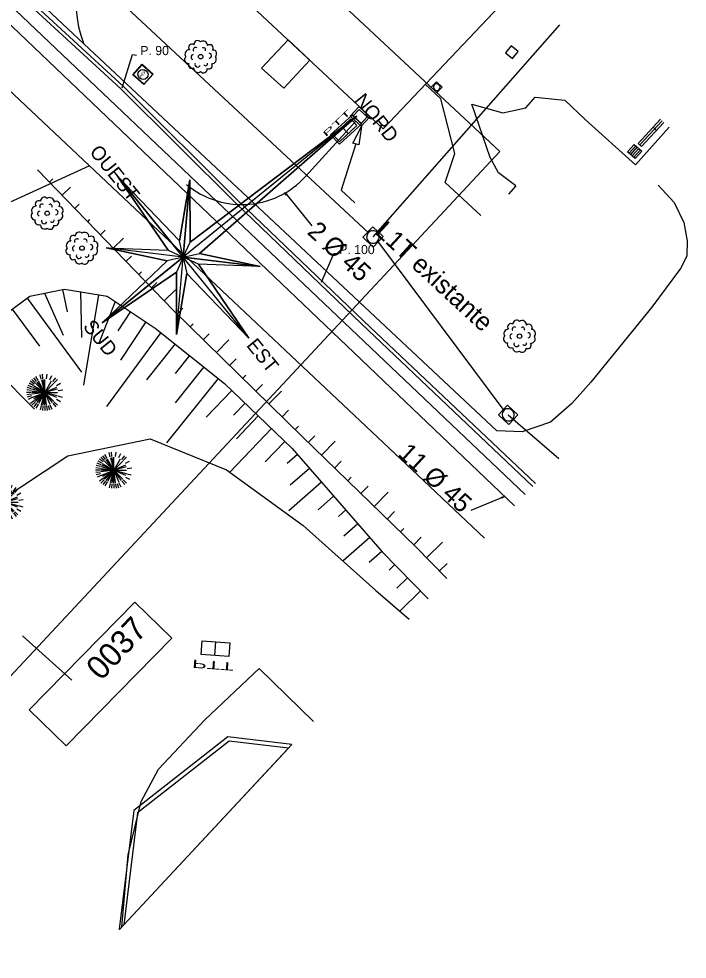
# Model space of a CAD drawing. Extents: x 343997 to 344255, y 298512 to 298767.
# Drawn here: x 344218.9 to 344255.3, y 298581.7 to 298632.9 of the extents above; entities that cross this region are included whole.
import ezdxf

# ---------------------------------------------------------------- set-up
doc = ezdxf.new("R2010")
doc.units = 0
for name, color, linetype in [('Default', 7, 'Continuous'), ('DH_CADRE -CARTOUCHE', 7, 'Continuous'), ('DH_CADRE-CARTOUCHE', 7, 'Continuous'), ('DH_CADRE-CARTOUCHE-NORD', 7, 'Continuous'), ('DH_NORD', 7, 'Continuous'), ('DH_TEXTE', 7, 'Continuous'), ('DIR-Projet VRD1', 7, 'Continuous'), ('EL-FOURR', 7, 'Continuous'), ('GO_DALLE', 7, 'Continuous'), ('IMM_VOIRIE VOIE FERREE', 7, 'Continuous'), ('MT-DONNEE', 7, 'Continuous'), ('O-Projet New VRD', 7, 'Continuous'), ('PC_REBAR', 7, 'Continuous'), ('PS_HIDDEN', 7, 'Continuous'), ('PS_OBJECT', 7, 'Continuous'), ('PS_PLATE', 7, 'Continuous'), ('RES_EAU', 7, 'Continuous'), ('RES_EAU PLUVIALE', 7, 'Continuous'), ('RES_MOYENNE TENSION', 7, 'Continuous')]:
    doc.layers.add(name, color=color, linetype=linetype)

# ---------------------------------------------------------------- blocks, each defined once
blk = doc.blocks.new('REG_INC')
at = {"layer": 'Default'}
for p, q in [((0, 0.1), (0.1, 0.1)), ((0, 0), (0, 0.1)), ((0.1, 0.1), (0.1, 0)), ((0.1, 0), (0, 0))]:
    blk.add_line(p, q, dxfattribs=at)
for centre, start, end in [((0.0498, 0.05), 135.00554, 180.00554), ((0.05, 0.0498), 90.00577, 135.00577), ((0.05, 0.05), 45.00687, 90.00687), ((0.0499, 0.0499), 0.00663, 45.00663), ((0.0501, 0.05), 180.00663, 225.00663), ((0.0499, 0.0498), 225.00686, 270.00686), ((0.0499, 0.05), 270.00577, 315.00577), ((0.0501, 0.0499), 315.00554, 0.00554)]:
    blk.add_arc(centre, 0.044, start, end, dxfattribs=at)
blk = doc.blocks.new('R3')
at = {"layer": 'Default'}
for p, q in [((0, 0.1), (0.1, 0.1)), ((0, 0), (0, 0.1)), ((0.1, 0), (0, 0)), ((0.1, 0.1), (0.1, 0))]:
    blk.add_line(p, q, dxfattribs=at)
blk = doc.blocks.new('RES_EAU')
at = {"layer": 'RES_EAU'}
for points in [[(0, 0), (0, 0.1), (0.1, 0.1), (0.1, 0)], [(0.0025, 0.0025), (0.0025, 0.0975), (0.0975, 0.0975), (0.0975, 0.0025)]]:
    blk.add_lwpolyline(points, close=True, dxfattribs=at)
blk.add_circle((0.05, 0.05), 0.035, dxfattribs=at)
blk.add_text('AEP', height=0.02, dxfattribs=at).set_placement((0.0224, 0.0448))
blk = doc.blocks.new('CT2')
at = {"layer": 'Default'}
blk.add_lwpolyline([(0, 0), (0.1, 0), (0.1, 0.1), (0, 0.1)], close=True, dxfattribs=at)
blk.add_lwpolyline([(0.05, 0.1), (0.05, 0)], dxfattribs=at)
blk.add_text('PTT', height=0.06, dxfattribs=at).set_placement((-0.03, 0.1425))
blk = doc.blocks.new('R5')
at = {"layer": 'Default'}
for p, q in [((0, 0.1), (0, 0)), ((0.1, 0.1), (0, 0.1)), ((0.02, 0.1), (0.02, 0)), ((0.04, 0.1), (0.04, 0)), ((0.06, 0.1), (0.06, 0)), ((0.08, 0.1), (0.08, 0)), ((0.1, 0), (0.1, 0.1)), ((0, 0), (0.1, 0)), ((0.06, 0), (0.06, 0))]:
    blk.add_line(p, q, dxfattribs=at)
blk = doc.blocks.new('ARB1')
at = {"layer": 'Default'}
blk.add_circle((0, 0), 0.0122, dxfattribs=at)
for centre, radius, start, end in [((-0.0471, 0.0503), 0.0183, 53.9554, 222.2066), ((-0.0153, 0.0664), 0.0211, 43.6925, 183.5969), ((0.0139, 0.0613), 0.0241, 358.4583, 125.1928), ((0.0501, 0.0468), 0.0183, 325.1444, 131.0175), ((-0.0613, 0.0139), 0.0241, 88.4583, 215.1928), ((-0.0373, -0.0024), 0.0149, 103.7092, 242.3465), ((-0.0276, 0.037), 0.0134, 52.4396, 209.5496), ((0.0164, 0.038), 0.0112, 330.5895, 133.7127), ((0.0458, 0.0052), 0.0137, 276.6214, 88.967), ((0.0613, -0.0139), 0.0241, 268.4583, 35.1928), ((0.0664, 0.0153), 0.0211, 313.6925, 93.5969), ((-0.0664, -0.0153), 0.0211, 133.6925, 273.5969), ((-0.0478, -0.0443), 0.019, 155.2243, 300.9377), ((-0.0163, -0.042), 0.0148, 159.5371, 338.1663), ((0.0271, -0.038), 0.0112, 210.5895, 13.7127), ((0.0448, -0.0483), 0.0188, 243.1323, 33.0297), ((-0.0139, -0.0613), 0.0241, 178.4583, 305.1928), ((0.0153, -0.0664), 0.0211, 223.6925, 3.5969)]:
    blk.add_arc(centre, radius, start, end, dxfattribs=at)
blk = doc.blocks.new('ARB2')
at = {"layer": 'Default'}
for p, q in [((-0.0575, 0.0453), (-0.0775, 0.0605)), ((-0.0513, 0.0525), (-0.0688, 0.0702)), ((-0.0438, 0.0589), (-0.0588, 0.0786)), ((-0.0356, 0.0642), (-0.0481, 0.0858)), ((-0.0181, 0.0716), (-0.0244, 0.0956)), ((-0.0088, 0.0736), (-0.0119, 0.0983)), ((0.0106, 0.0736), (0.0144, 0.0983)), ((0.0287, 0.0684), (0.0388, 0.0914)), ((0.0456, 0.0589), (0.0612, 0.0786)), ((0.0531, 0.0525), (0.0706, 0.0702)), ((-0.0731, 0), (-0.0981, 0)), ((-0.0725, 0.01), (-0.0969, 0.0133)), ((-0.0706, 0.0195), (-0.0944, 0.0259)), ((-0.0675, 0.0286), (-0.09, 0.0381)), ((-0.0631, 0.0373), (-0.0844, 0.0497)), ((0.065, 0.0373), (0.0862, 0.0497)), ((0.0744, 0.01), (0.0987, 0.0133)), ((-0.0725, -0.01), (-0.0969, -0.0133)), ((-0.0706, -0.0195), (-0.0944, -0.0259)), ((-0.0675, -0.0287), (-0.09, -0.0383)), ((-0.0575, -0.0455), (-0.0775, -0.0605)), ((0.065, -0.0373), (0.0862, -0.0498)), ((0.0725, -0.0195), (0.0963, -0.0259)), ((-0.0513, -0.0527), (-0.0688, -0.0702)), ((-0.0438, -0.0591), (-0.0588, -0.0787)), ((-0.0356, -0.0644), (-0.0481, -0.0859)), ((-0.0181, -0.0717), (-0.0244, -0.0956)), ((-0.0088, -0.0737), (-0.0119, -0.0983)), ((0.0013, -0.0741), (0.0013, -0.0989)), ((0.0106, -0.0737), (0.0144, -0.0983)), ((0.02, -0.0717), (0.0263, -0.0956)), ((0.0287, -0.0686), (0.0388, -0.0916)), ((0.0456, -0.0591), (0.0612, -0.0787)), ((0.0531, -0.0527), (0.0706, -0.0702))]:
    blk.add_line(p, q, dxfattribs=at)
for points in [[(-0.0688, 0.0091), (0.0013, 0), (-0.0338, 0.0608)], [(-0.0419, 0.0556), (0.0013, 0), (-0.0638, 0.0269)], [(-0.0169, 0.0677), (0.0013, 0), (-0.06, 0.035)], [(0.0013, 0.0008), (0.0013, 0), (-0.0081, 0.0695)], [(0.0362, 0.0608), (0.0013, 0), (0.0013, 0.0702)], [(-0.0487, -0.0497), (0.0013, 0), (-0.0694, 0)], [(-0.0638, -0.0269), (0.0013, 0), (-0.0688, -0.0092)], [(-0.0487, 0.0495), (0.0013, 0), (-0.0669, 0.0181)], [(-0.0169, -0.0678), (0.0013, 0), (-0.06, -0.0352)], [(-0.0544, -0.0428), (0.0013, 0), (-0.0338, -0.0608)], [(-0.0081, -0.0695), (0.0013, 0), (-0.0419, -0.0558)], [(0.0013, -0.0702), (0.0013, 0), (0, 0)], [(0.0656, 0.0269), (0.0013, 0), (0.0506, 0.0495)], [(0.0688, 0.0181), (0.0013, 0), (0.0713, 0)], [(0.0438, -0.0558), (0.0013, 0), (0.0656, -0.0269)], [(0.0506, -0.0497), (0.0013, 0), (0.0688, -0.0181)], [(0.01, -0.0695), (0.0013, 0), (0.0281, -0.0648)], [(0.0019, 0), (0.0013, 0), (0.0013, -0.0009)]]:
    blk.add_lwpolyline(points, dxfattribs=at)

msp = doc.modelspace()

# ---------------------------------------------------------------- linework, layer by layer
at = {"layer": 'DH_CADRE -CARTOUCHE'}
for points in [[(343997.309, 298660.673), (344147.183, 298520.807), (344245.09, 298625.72), (344095.215, 298765.586)], [(344246.085, 298634.723), (344238.071, 298642.203), (344230.773, 298634.4), (344238.733, 298626.952)], [(344224.371, 298583.346), (344233.763, 298593.411), (344230.272, 298593.836), (344225.143, 298589.82), (344224.357, 298583.363)]]:
    msp.add_lwpolyline(points, close=True, dxfattribs=at)
at = {"layer": 'DH_CADRE-CARTOUCHE'}
for points in [[(344173.884, 298668.877), (344175.641, 298668.318), (344176.928, 298667.79), (344178.107, 298666.872), (344194.798, 298651.17), (344217.989, 298629.411), (344240.944, 298607.781), (344244.256, 298604.654)], [(344253.72, 298623.882), (344254.601, 298622.951), (344255.115, 298621.851), (344255.304, 298620.858), (344255.289, 298620.014), (344254.937, 298619.35), (344253.379, 298617.242), (344250.056, 298613.162), (344249.016, 298611.996), (344247.858, 298610.985), (344246.303, 298610.451), (344244.928, 298610.512), (344219.242, 298634.584), (344198.152, 298654.571), (344186.596, 298665.445)]]:
    msp.add_lwpolyline(points, dxfattribs=at)
msp.add_arc((344228.199, 298633.832), 6.201, 132.5787, 200.9263, dxfattribs=at)
at = {"layer": 'DH_CADRE-CARTOUCHE-NORD'}
for p, q in [((344248.345, 298632.614), (344238.179, 298621.064)), ((344215.714, 298621.751), (344222.758, 298624.96)), ((344238.423, 298620.831), (344245.304, 298611.605)), ((344245.555, 298611.367), (344248.309, 298608.997))]:
    msp.add_line(p, q, dxfattribs=at)
msp.add_lwpolyline([(344237.935, 298621.298), (344195.027, 298661.228), (344177.442, 298676.027), (344168.974, 298681.087)], dxfattribs=at)
at = {"layer": 'DH_NORD'}
for p, q in [((344237.303, 298627.646), (344223.425, 298616.384)), ((344237.303, 298627.646), (344228.217, 298620.788)), ((344224.257, 298624.374), (344227.011, 298620.345)), ((344231.415, 298615.553), (344224.257, 298624.374)), ((344227.465, 298615.748), (344228.206, 298624.179)), ((344228.206, 298624.179), (344227.644, 298620.859)), ((344223.634, 298620.469), (344226.962, 298619.77)), ((344232.037, 298619.458), (344223.634, 298620.469)), ((344232.037, 298619.458), (344228.721, 298620.167)), ((344231.415, 298615.553), (344228.673, 298619.592)), ((344223.425, 298616.384), (344227.466, 298619.149)), ((344227.465, 298615.748), (344228.039, 298619.078))]:
    msp.add_line(p, q, dxfattribs=at)
for points in [[(344237.303, 298627.646), (344228.721, 298620.167), (344232.037, 298619.458), (344228.673, 298619.592), (344231.415, 298615.553), (344228.039, 298619.078), (344227.465, 298615.748), (344227.466, 298619.149), (344223.425, 298616.384), (344226.962, 298619.77), (344223.634, 298620.469), (344227.011, 298620.345), (344224.257, 298624.374), (344227.644, 298620.859), (344228.206, 298624.179), (344228.217, 298620.788)], [(344237.303, 298627.646), (344227.836, 298619.963), (344228.721, 298620.167), (344228.721, 298620.167)], [(344224.257, 298624.374), (344227.836, 298619.963), (344227.644, 298620.859), (344227.644, 298620.859)], [(344228.206, 298624.179), (344227.836, 298619.963), (344228.217, 298620.788), (344228.217, 298620.788)], [(344223.634, 298620.469), (344227.011, 298620.345), (344227.836, 298619.963)], [(344223.425, 298616.384), (344227.836, 298619.963), (344226.962, 298619.77), (344226.962, 298619.77)], [(344227.465, 298615.748), (344227.836, 298619.963), (344227.466, 298619.149), (344227.466, 298619.149)], [(344232.037, 298619.458), (344228.673, 298619.592), (344227.836, 298619.963)], [(344231.415, 298615.553), (344227.836, 298619.963), (344228.039, 298619.078), (344228.039, 298619.078)]]:
    msp.add_lwpolyline(points, close=True, dxfattribs=at)
at = {"layer": 'DIR-Projet VRD1'}
msp.add_line((344180.02, 298669.219), (344245.896, 298606.412), dxfattribs=at)
msp.add_lwpolyline([(344237.239, 298627.37), (344234.681, 298624.557)], dxfattribs=at)
msp.add_arc((344231.037, 298627.539), 4.709, 230.0068, 320.7025, dxfattribs=at)
at = {"layer": 'EL-FOURR'}
for points in [[(344246.89, 298607.477), (344237.55, 298616.33), (344230.72, 298622.88), (344224.44, 298629.13), (344216.3, 298636.61), (344208.4, 298644.02), (344200.94, 298650.94), (344194.75, 298656.93), (344187.61, 298663.75), (344182.92, 298668.55), (344179.08, 298673.97)], [(344179.26, 298674.06), (344183.08, 298668.68), (344187.75, 298663.89), (344194.89, 298657.08), (344201.08, 298651.08), (344208.54, 298644.17), (344216.43, 298636.76), (344224.58, 298629.27), (344230.85, 298623.02), (344237.69, 298616.48), (344247.03, 298607.627)]]:
    msp.add_lwpolyline(points, dxfattribs=at)
at = {"layer": 'GO_DALLE'}
for points in [[(344234.735, 298630.693), (344233.554, 298631.798), (344232.114, 298630.26), (344233.317, 298629.178)], [(344237.059, 298627.718), (344237.552, 298627.211), (344236.363, 298626.128), (344235.87, 298626.636)]]:
    msp.add_lwpolyline(points, close=True, dxfattribs=at)
for points in [[(344244.061, 298622.24), (344242.123, 298624.038), (344242.65, 298625.603), (344241.87, 298628.59), (344241.032, 298629.382)], [(344245.974, 298623.847), (344245.03, 298624.565), (344244.572, 298625.398), (344243.566, 298628.301), (344245.252, 298627.821), (344246.504, 298628.1), (344247.021, 298628.689), (344248.634, 298628.526), (344249.747, 298627.457), (344252.49, 298624.988), (344254.319, 298627.04)], [(344245.974, 298623.847), (344245.561, 298623.405)]]:
    msp.add_lwpolyline(points, dxfattribs=at)
at = {"layer": 'IMM_VOIRIE VOIE FERREE'}
msp.add_line((344221.778, 298596.916), (344219.076, 298599.34), dxfattribs=at)
msp.add_lwpolyline([(344224.492, 298583.477), (344224.843, 298587.413), (344225.548, 298590.315), (344226.496, 298592.077), (344229.019, 298594.765), (344231.976, 298597.554), (344234.941, 298594.673)], dxfattribs=at)
at = {"layer": 'MT-DONNEE'}
for points in [[(344224.52, 298629.18), (344225.08, 298631), (344225.3, 298630.97)], [(344235.38, 298618.6), (344236.04, 298620.16), (344236.19, 298620.16)]]:
    msp.add_lwpolyline(points, dxfattribs=at)
at = {"layer": 'O-Projet New VRD'}
for points in [[(344237.42, 298628.155), (344238.007, 298627.614), (344237.533, 298627.099), (344236.944, 298627.641), (344237.419, 298628.156)], [(344237.428, 298628.017), (344237.869, 298627.611), (344237.531, 298627.242), (344237.089, 298627.649), (344237.428, 298628.017)], [(344237.248, 298626.13), (344236.449, 298623.607)], [(344236.449, 298623.607), (344237.185, 298622.93)], [(344233.481, 298623.354), (344234.842, 298621.676)], [(344245.186, 298606.861), (344243.521, 298606.159)]]:
    msp.add_lwpolyline(points, dxfattribs=at)
for points in [[(344237.089, 298626.18), (344237.55, 298627.084), (344237.407, 298626.08)], [(344233.458, 298623.335), (344233.368, 298623.494), (344233.505, 298623.373)], [(344245.174, 298606.888), (344245.352, 298606.931), (344245.197, 298606.833)]]:
    msp.add_lwpolyline(points, close=True, dxfattribs=at)
at = {"layer": 'PS_HIDDEN'}
msp.add_lwpolyline([(344224.608, 298583.6), (344233.577, 298593.212), (344230.336, 298593.606), (344225.35, 298589.703)], close=True, dxfattribs=at)
at = {"layer": 'PS_OBJECT'}
for p, q in [((344220.55, 298624.054), (344220.742, 298624.239)), ((344221.245, 298623.334), (344221.695, 298623.769)), ((344221.94, 298622.615), (344222.178, 298622.844)), ((344222.635, 298621.896), (344222.76, 298622.017)), ((344223.33, 298621.176), (344223.594, 298621.432)), ((344224.025, 298620.457), (344224.583, 298620.996)), ((344224.72, 298619.737), (344225.015, 298620.022)), ((344225.415, 298619.018), (344225.57, 298619.168)), ((344226.11, 298618.299), (344226.405, 298618.584)), ((344220.278, 298618.006), (344221.294, 298615.721)), ((344221.257, 298618.208), (344221.511, 298616.983)), ((344222.243, 298618.084), (344222.292, 298615.584)), ((344223.23, 298617.919), (344222.408, 298612.986)), ((344226.805, 298617.579), (344227.428, 298618.181)), ((344219.33, 298617.732), (344222.289, 298613.7)), ((344224.136, 298617.551), (344223.218, 298615.225)), ((344218.523, 298617.14), (344220.003, 298615.124)), ((344224.969, 298616.997), (344224.276, 298615.956)), ((344227.505, 298616.865), (344227.824, 298617.191)), ((344225.802, 298616.443), (344224.417, 298614.361)), ((344228.22, 298616.165), (344228.388, 298616.337)), ((344226.615, 298615.862), (344223.665, 298611.822)), ((344228.935, 298615.466), (344229.255, 298615.793)), ((344216.214, 298615.237), (344219.734, 298611.684)), ((344227.396, 298615.237), (344225.835, 298613.283)), ((344229.65, 298614.766), (344230.325, 298615.456)), ((344228.177, 298614.613), (344227.397, 298613.636)), ((344230.365, 298614.066), (344230.721, 298614.43)), ((344228.959, 298613.988), (344227.398, 298612.035)), ((344229.74, 298613.364), (344226.93, 298609.848)), ((344231.08, 298613.367), (344231.249, 298613.54)), ((344230.488, 298612.701), (344229.085, 298611.24)), ((344231.794, 298612.667), (344232.152, 298613.032)), ((344232.509, 298611.968), (344233.188, 298612.66)), ((344231.21, 298612.008), (344230.578, 298611.351)), ((344233.224, 298611.268), (344233.582, 298611.634)), ((344231.931, 298611.316), (344230.735, 298610.07)), ((344232.653, 298610.623), (344230.384, 298608.261)), ((344233.939, 298610.568), (344234.128, 298610.761)), ((344234.655, 298609.87), (344235.012, 298610.238)), ((344233.374, 298609.93), (344232.299, 298608.811)), ((344235.373, 298609.174), (344236.127, 298609.95)), ((344234.067, 298609.21), (344233.513, 298608.727)), ((344236.091, 298608.477), (344236.449, 298608.846)), ((344234.724, 298608.456), (344233.674, 298607.54)), ((344235.381, 298607.702), (344233.589, 298606.14)), ((344236.809, 298607.781), (344236.998, 298607.975)), ((344237.527, 298607.084), (344237.925, 298607.494)), ((344238.245, 298606.388), (344239.001, 298607.167)), ((344236.038, 298606.948), (344235.189, 298606.208)), ((344236.696, 298606.193), (344236.293, 298605.843)), ((344238.963, 298605.691), (344239.362, 298606.102)), ((344237.353, 298605.439), (344236.59, 298604.775)), ((344239.681, 298604.995), (344239.87, 298605.19)), ((344238.01, 298604.685), (344236.564, 298603.425)), ((344240.399, 298604.298), (344240.799, 298604.71)), ((344241.104, 298603.589), (344241.966, 298604.441)), ((344238.667, 298603.931), (344237.982, 298603.334)), ((344239.365, 298603.215), (344239.057, 298602.914)), ((344241.807, 298602.878), (344242.217, 298603.282)), ((344240.065, 298602.5), (344239.481, 298601.929)), ((344240.764, 298601.785), (344239.658, 298600.703))]:
    msp.add_line(p, q, dxfattribs=at)
for points in [[(344242.214, 298602.466), (344240.509, 298604.191), (344234.347, 298610.169), (344227.328, 298617.038), (344219.907, 298624.72)], [(344184.947, 298581.398), (344185.091, 298582.452), (344184.802, 298583.514), (344186.691, 298584.063), (344189.735, 298586.719), (344192.676, 298590.389), (344195.465, 298594.065), (344199.099, 298597.718), (344203.435, 298602.18), (344207.43, 298606.195), (344211.519, 298610.49), (344214.324, 298613.364), (344217.026, 298616.042), (344219.477, 298617.84), (344221.365, 298618.23), (344223.701, 298617.841), (344226.31, 298616.105), (344230.086, 298613.088), (344233.778, 298609.542), (344238.683, 298603.912), (344241.181, 298601.359)], [(344163.934, 298561.868), (344170.201, 298566.564), (344176.522, 298569.299), (344180.879, 298572.338), (344183.313, 298574.136), (344185.048, 298576.477), (344188.051, 298580.099), (344191.638, 298583.956), (344195.571, 298587.909), (344198.338, 298590.807), (344202.379, 298595.055), (344209.468, 298599.999), (344216.32, 298605.698), (344221.544, 298609.146), (344226.03, 298610.067), (344230.196, 298608.376), (344234.376, 298605.349), (344238.337, 298601.801), (344240.148, 298600.253)]]:
    msp.add_lwpolyline(points, dxfattribs=at)
at = {"layer": 'PS_PLATE'}
msp.add_lwpolyline([(344221.463, 298593.336), (344219.453, 298595.304), (344225.199, 298601.174), (344227.212, 298599.209)], close=True, dxfattribs=at)
at = {"layer": 'RES_EAU PLUVIALE'}
for p, q in [((344252.631, 298626.162), (344253.849, 298627.479)), ((344253.943, 298627.39), (344252.726, 298626.075)), ((344254.037, 298627.302), (344252.821, 298625.987)), ((344253.637, 298626.87), (344253.448, 298627.045)), ((344252.821, 298625.987), (344252.631, 298626.162))]:
    msp.add_line(p, q, dxfattribs=at)
at = {"layer": 'RES_MOYENNE TENSION'}
msp.add_line((344181.027, 298669.218), (344246.474, 298607.032), dxfattribs=at)

# ---------------------------------------------------------------- block references
at = {"layer": 'DH_CADRE-CARTOUCHE-NORD', "xscale": 4.855426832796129, "yscale": -4.812391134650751, "rotation": -129.18204000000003}
msp.add_blockref('R3', (344246.088, 298631.171), dxfattribs=at)
at = {"layer": 'DH_NORD'}
for p, xscale, yscale, rotation in [((344236.364, 298626.254), 12.923812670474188, 4.884434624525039, 43.410689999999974), ((344228.872, 298599.061), 15.043979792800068, -7.39125329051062, -4.26447000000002)]:
    msp.add_blockref('CT2', p, dxfattribs=dict(at, xscale=xscale, yscale=yscale, rotation=rotation))
at = {"layer": 'PC_REBAR', "xscale": 10, "yscale": 10}
for name, p in [('ARB1', (344228.788, 298630.885)), ('ARB1', (344220.426, 298622.356)), ('ARB1', (344222.322, 298620.459)), ('ARB1', (344246.168, 298615.658)), ('ARB2', (344220.285, 298612.601)), ('ARB2', (344224.044, 298608.361)), ('ARB2', (344218.129, 298606.626))]:
    msp.add_blockref(name, p, dxfattribs=at)
at = {"layer": 'RES_EAU', "xscale": 7.694590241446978, "yscale": 8.043178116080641, "rotation": 48.23441999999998}
msp.add_blockref('RES_EAU', (344225.691, 298629.362), dxfattribs=at)
at = {"layer": 'RES_EAU PLUVIALE'}
for name, p, xscale, yscale, rotation in [('REG_INC', (344241.956, 298629.218), 4.34786203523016, 4.098313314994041, 135.50138999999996), ('R5', (344252.417, 298626.111), 5.6564083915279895, -5.3769215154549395, -42.03071999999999), ('REG_INC', (344237.631, 298621.048), 7.682929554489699, 7.8232462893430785, -43.684650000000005), ('REG_INC', (344245.024, 298611.369), 7.687785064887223, 7.26072247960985, -42.80049)]:
    msp.add_blockref(name, p, dxfattribs=dict(at, xscale=xscale, yscale=yscale, rotation=rotation))

# ---------------------------------------------------------------- texts
at = {"layer": 'DH_NORD'}
for s, p in [('NORD', (344237.129, 298628.494)), ('OUEST', (344222.698, 298625.685)), ('SUD', (344222.344, 298616.167)), ('EST', (344231.247, 298615.149))]:
    msp.add_text(s, height=0.768, rotation=309.0577, dxfattribs=at).set_placement(p)
at = {"layer": 'DH_TEXTE'}
msp.add_text('0037', height=1.2769, rotation=46.8875, dxfattribs=at).set_placement((344223.364, 298596.844))
at = {"layer": 'MT-DONNEE'}
for s, p in [('P. 90', (344225.5, 298630.97)), ('P. 100', (344236.34, 298620.13))]:
    msp.add_text(s, height=0.5, dxfattribs=at).set_placement(p)
at = {"layer": 'O-Projet New VRD'}
for s, height, p in [('L1T existante', 1.00027, (344238.246, 298621.279)), ('2 Ø 45', 1.0003, (344234.546, 298621.273)), ('11 Ø 45', 1.0003, (344239.492, 298609.194))]:
    msp.add_text(s, height=height, rotation=317.3672, dxfattribs=at).set_placement(p)

doc.saveas('drawing.dxf')
